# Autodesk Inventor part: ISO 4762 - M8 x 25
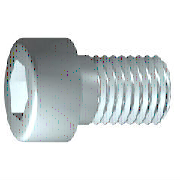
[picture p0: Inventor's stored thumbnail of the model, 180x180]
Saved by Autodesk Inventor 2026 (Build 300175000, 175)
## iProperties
IsCustomPart: 1
Created: 2021-02
Part Number: ISO 4762 - M8 x 25
Material: Stainless Steel, 440C
Description: Hexagon Socket Head Cap Screw
Document SubType Name: Modeling
Standard: ISO 4762
Designer: Lars Bertram Pedersen
Standard Revision: Fourth edition 2004-03-01
Standards Organization: ISO
Language: en-US
Size Designation: M8 x 25
Categories: <MemberInstance><Categories><Category DisplayName="Fasteners" InternalName="e4da775c-781d-43d5-af7c-5136215cf5a6" Mnemonic="FSTN"><Category DisplayName="Bolts"
Density: 7.75 g/cm^3
Appearance: Semi-Polished
Author: Lars Bertram Pedersen
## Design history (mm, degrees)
workplane "Work Plane1"
fillet "Fillet2" dims "d30" = 0.1 (= R)
revolve "Body" stored, may be unused: angle "d10" = 90 deg
sketch "Sketch2"
  geometry: L1 (0, -9.1)-(0, 9.1) reference; L2 (-9.1, 0)-(9.1, 0) reference; L3 (3.464, 0)-(1.732, -3); L4 (1.732, -3)-(-1.732, -3); L5 (-1.732, -3)-(-3.464, 0); L6 (-3.464, 0)-(-1.732, 3); L7 (-1.732, 3)-(1.732, 3); L8 (1.732, 3)-(3.464, 0); 2 further points
  constraints: 12 end point, 1 coincident, 1 horizontal alignment, 1 point on line, 12 other
extrude "Slot" join sketch "Sketch2" stored distance "d11" = 10; taper "d12" = 0 deg
body "Solid1"
fillet "Fillet1" dims "d17" = 0.8 (= RR)
feature "Thread" dims "d13" = 21.875 (= GEL), "d14" = 0
chamfer "Chamfer1" distance "d15" = 0.76681 (= -0.5 x SPD + 0.5 x GD); stored, may be unused: second distance "d16" = 0.76681 (= GUL), angle "d27" = 45 deg
sketch "Sketch1"
  geometry: L1 (-2, 0)-(25, 0); L2 (25, 0)-(25, 4); L3 (25, 4)-(3.125, 4); L4 (3.125, 4)-(2.358, 4); L5 (2.358, 4)-(0, 4); L6 (0, 4)-(0, 6.5); L7 (0, 6.5)-(-8, 6.5); L8 (-8, 6.5)-(-8, 3.464); L9 (-8, 3.464)-(-4, 3.464); L10 (-4, 3.464)-(-2, 0); L11 (-14.6, 0)-(31.6, 0) reference; L12 (0, -1.3)-(0, 7.8) reference; L13 (3.125, 4)-(0, 4)
  constraints: 22 end point, 6 parallel, 2 collinear, 2 perpendicular, 1 horizontal, 1 point on line
  dimensions: "d1" = 21.875 distance from line of L3.end L2 (= GEL); "d2" = 0.76691 distance of L4.end L3.end (computed from GAL); "d3" = 8 distance between parallel lines of L8 L6 (= KOH); "d4" = 4 distance of L8.end L9.end (= INTI); "d5" = 60 deg angle of L10 L1; "d6" = 8 diameter of L3 L1 (= GD); "d7" = 8 diameter of L5 L1 (= BDM); "d8" = 6.9282 diameter of L9 L1 (= 1.1547 x SW); "d9" = 13 diameter of L7 L1 (= KOD); "d26" = 25 distance between parallel lines of L12 L2 (= NLG)
other parameters: "GD" = 8 [user parameter; used in 2 equation terms], "NLG" = 25 [user parameter; used in 1 equation term], "GEL" = 21.875 [user parameter; used in 2 equation terms], "KOD" = 13 [user parameter; used in 1 equation term], "KOH" = 8 [user parameter; used in 1 equation term], "INTI" = 4 [user parameter; used in 1 equation term], "GAL" = 0.76681 (= 0.61345 x PTC) [user parameter; used in 1 equation term], "GUL" = 0.76681 (= 0.61345 x PTC) [user parameter; used in 1 equation term], "BDM" = 8 (= NND) [user parameter; used in 1 equation term], "SW" = 6 [user parameter; used in 2 equation terms], "RR" = 0.8 [user parameter; used in 1 equation term], "SPD" = 6.46637 (= NND - 1.2269 x PTC) [user parameter; used in 1 equation term], "d19" = 0, "d28" = 0, "d29" = 0, "R" = 0.1 [user parameter; used in 1 equation term], "TOA" = 30 deg [user parameter], "GD1" = 6.46637 (= THREADDIA - 1.2269 x PTC) [user parameter], "THREADDIA" = 8 [user parameter; used in 1 equation term], "FAWI" = 45 deg [user parameter], "TPU" = 8 (computed from PTC) [user parameter], "PTC" = 1.25 [user parameter; used in 5 equation terms], "NND" = 8 [user parameter; used in 2 equation terms], "E0" = 6.93 (= 1.155 x SW) [user parameter]
